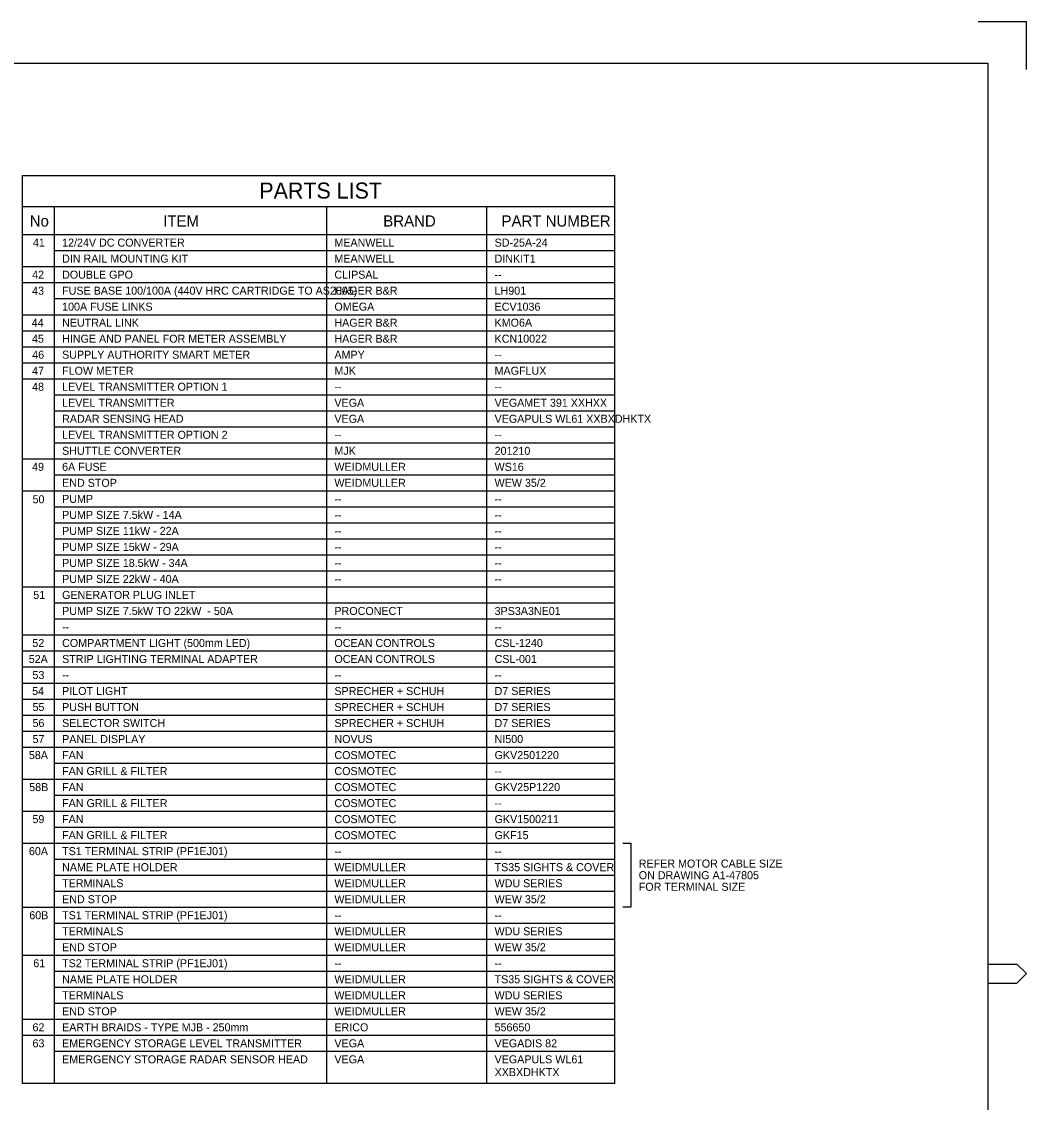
# Model space of a CAD drawing. Extents: x 0 to 841, y 0 to 594.
# Drawn here: x 527.4 to 841, y 256.6 to 594 of the extents above; entities that cross this region are included whole.
import ezdxf

# ---------------------------------------------------------------- set-up
doc = ezdxf.new("R2010")
doc.units = 0
for name, color, linetype in [('A1BORDER', 7, 'Continuous'), ('Default', 7, 'Continuous'), ('Level 1', 7, 'Continuous')]:
    doc.layers.add(name, color=color, linetype=linetype)

msp = doc.modelspace()

# ---------------------------------------------------------------- linework, layer by layer
at = {"layer": 'A1BORDER'}
for p, q in [((826, 594), (841, 594)), ((841, 579), (841, 594)), ((28, 581), (829, 581)), ((829, 581), (829, 15)), ((829, 299.76), (838, 299.76)), ((838, 299.76), (841, 296.76)), ((829, 293.76), (838, 293.76)), ((838, 293.76), (841, 296.76))]:
    msp.add_line(p, q, dxfattribs=at)
at = {"layer": 'Default'}
for p, q in [((537.5, 472.5), (712.5, 472.5)), ((537.5, 462.5), (712.5, 462.5)), ((527.5, 277.5), (712.5, 277.5)), ((537.5, 272.5), (712.5, 272.5))]:
    msp.add_line(p, q, dxfattribs=at)
msp.add_lwpolyline([(715, 337.5), (717.5, 337.5), (717.5, 317.5), (715, 317.5)], dxfattribs=at)
at = {"layer": 'Level 1'}
for p, q in [((527.5, 546), (527.5, 262.5)), ((527.5, 546), (712.5, 546)), ((712.5, 262.5), (712.5, 546)), ((527.5, 536.25), (712.5, 536.25)), ((537.5, 536.25), (537.5, 262.5)), ((622.5, 536.25), (622.5, 262.5)), ((672.5, 536.25), (672.5, 262.5)), ((527.5, 527.5), (712.5, 527.5)), ((537.5, 522.5), (712.5, 522.5)), ((527.5, 517.5), (712.5, 517.5)), ((527.5, 512.5), (712.5, 512.5)), ((537.5, 507.5), (712.5, 507.5)), ((527.5, 502.5), (712.5, 502.5)), ((527.5, 497.5), (712.5, 497.5)), ((527.5, 492.5), (712.5, 492.5)), ((527.5, 487.5), (712.5, 487.5)), ((527.5, 482.5), (712.5, 482.5)), ((537.5, 477.5), (712.5, 477.5)), ((537.5, 467.5), (712.5, 467.5)), ((527.5, 457.5), (712.5, 457.5)), ((537.5, 452.5), (712.5, 452.5)), ((527.5, 447.5), (712.5, 447.5)), ((537.5, 442.5), (712.5, 442.5)), ((537.5, 437.5), (712.5, 437.5)), ((537.5, 432.5), (712.5, 432.5)), ((537.5, 427.5), (712.5, 427.5)), ((537.5, 422.5), (712.5, 422.5)), ((527.5, 417.5), (712.5, 417.5)), ((537.5, 412.5), (712.5, 412.5)), ((537.5, 407.5), (712.5, 407.5)), ((527.5, 402.5), (712.5, 402.5)), ((527.5, 397.5), (712.5, 397.5)), ((527.5, 392.5), (712.5, 392.5)), ((527.5, 387.5), (712.5, 387.5)), ((527.5, 382.5), (712.5, 382.5)), ((527.5, 377.5), (712.5, 377.5)), ((527.5, 372.5), (712.5, 372.5)), ((527.5, 367.5), (712.5, 367.5)), ((537.5, 362.5), (712.5, 362.5)), ((527.5, 357.5), (712.5, 357.5)), ((537.5, 352.5), (712.5, 352.5)), ((527.5, 347.5), (712.5, 347.5)), ((537.5, 342.5), (712.5, 342.5)), ((527.5, 337.5), (712.5, 337.5)), ((537.5, 332.5), (712.5, 332.5)), ((537.5, 327.5), (712.5, 327.5)), ((537.5, 322.5), (712.5, 322.5)), ((527.5, 317.5), (712.5, 317.5)), ((537.5, 312.5), (712.5, 312.5)), ((537.5, 307.5), (712.5, 307.5)), ((527.5, 302.5), (712.5, 302.5)), ((537.5, 297.5), (712.5, 297.5)), ((537.5, 292.5), (712.5, 292.5)), ((537.5, 287.5), (712.5, 287.5)), ((527.5, 282.5), (712.5, 282.5)), ((712.5, 262.5), (527.5, 262.5))]:
    msp.add_line(p, q, dxfattribs=at)

# ---------------------------------------------------------------- texts
at = {"layer": 'Default'}
for s, p in [('LEVEL TRANSMITTER OPTION 1', (540, 478.75)), ('LEVEL TRANSMITTER', (540, 473.75)), ('VEGA', (625, 473.75)), ('VEGAMET 391 XXHXX', (675, 473.75)), ('RADAR SENSING HEAD', (540, 468.75)), ('VEGA', (625, 468.75)), ('VEGAPULS WL61 XXBXDHKTX', (675, 468.75)), ('LEVEL TRANSMITTER OPTION 2', (540, 463.75)), ('SHUTTLE CONVERTER', (540, 458.75)), ('MJK', (625, 458.75)), ('201210', (675, 458.75)), ('PUMP', (540, 443.75)), ('COMPARTMENT LIGHT (500mm LED)', (540, 398.75)), ('OCEAN CONTROLS', (625, 398.75)), ('CSL-1240', (675, 398.75)), ('STRIP LIGHTING TERMINAL ADAPTER', (540, 393.75)), ('OCEAN CONTROLS', (625, 393.75)), ('CSL-001', (675, 393.75)), ('62', (530.76, 278.75)), ('63', (530.76, 273.75)), ('EMERGENCY STORAGE LEVEL TRANSMITTER', (540, 273.75)), ('VEGA', (625, 273.75)), ('VEGADIS 82', (675, 273.75)), ('EMERGENCY STORAGE RADAR SENSOR HEAD', (540, 268.75)), ('VEGA', (625, 268.75)), ('VEGAPULS WL61', (675, 268.75)), ('XXBXDHKTX', (675, 264.75))]:
    msp.add_text(s, height=2.5, dxfattribs=at).set_placement(p)
at = {"layer": 'Level 1'}
for s, height, p in [('PARTS LIST', 5, (601.57, 538.75)), ('No', 3.5, (529.89, 530)), ('ITEM', 3.5, (571.54, 530)), ('BRAND', 3.5, (640.25, 530)), ('PART NUMBER', 3.5, (677.16, 530)), ('41', 2.5, (530.88, 523.75)), ('12/24V DC CONVERTER', 2.5, (540, 523.75)), ('MEANWELL', 2.5, (625, 523.75)), ('SD-25A-24', 2.5, (675, 523.75)), ('DIN RAIL MOUNTING KIT', 2.5, (540, 518.75)), ('MEANWELL', 2.5, (625, 518.75)), ('DINKIT1', 2.5, (675, 518.75)), ('42', 2.5, (530.66, 513.75)), ('DOUBLE GPO', 2.5, (540, 513.75)), ('CLIPSAL', 2.5, (625, 513.75)), ('--', 2.5, (675, 513.75)), ('43', 2.5, (530.63, 508.75)), ('FUSE BASE 100/100A (440V HRC CARTRIDGE TO AS2005)', 2.5, (540, 508.75)), ('HAGER B&R', 2.5, (625, 508.75)), ('LH901', 2.5, (675, 508.75)), ('100A FUSE LINKS', 2.5, (540, 503.75)), ('OMEGA', 2.5, (625, 503.75)), ('ECV1036', 2.5, (675, 503.75)), ('44', 2.5, (530.51, 498.75)), ('NEUTRAL LINK', 2.5, (540, 498.75)), ('HAGER B&R', 2.5, (625, 498.75)), ('KMO6A', 2.5, (675, 498.75)), ('45', 2.5, (530.59, 493.75)), ('HINGE AND PANEL FOR METER ASSEMBLY', 2.5, (540, 493.75)), ('HAGER B&R', 2.5, (625, 493.75)), ('KCN10022', 2.5, (675, 493.75)), ('46', 2.5, (530.66, 488.75)), ('SUPPLY AUTHORITY SMART METER', 2.5, (540, 488.75)), ('AMPY', 2.5, (625, 488.75)), ('--', 2.5, (675, 488.75)), ('47', 2.5, (530.63, 483.75)), ('FLOW METER', 2.5, (540, 483.75)), ('MJK', 2.5, (625, 483.75)), ('MAGFLUX', 2.5, (675, 483.75)), ('48', 2.5, (530.63, 478.75)), ('--', 2.5, (625, 478.75)), ('--', 2.5, (675, 478.75)), ('--', 2.5, (625, 463.75)), ('--', 2.5, (675, 463.75)), ('49', 2.5, (530.63, 453.75)), ('6A FUSE', 2.5, (540, 453.75)), ('WEIDMULLER', 2.5, (625, 453.75)), ('WS16', 2.5, (675, 453.75)), ('END STOP', 2.5, (540, 448.75)), ('WEIDMULLER', 2.5, (625, 448.75)), ('WEW 35/2', 2.5, (675, 448.75)), ('50', 2.5, (530.76, 443.62)), ('--', 2.5, (625, 443.75)), ('--', 2.5, (675, 443.75)), ('PUMP SIZE 7.5kW - 14A', 2.5, (540, 438.75)), ('--', 2.5, (625, 438.75)), ('--', 2.5, (675, 438.75)), ('PUMP SIZE 11kW - 22A', 2.5, (540, 433.75)), ('--', 2.5, (625, 433.75)), ('--', 2.5, (675, 433.75)), ('PUMP SIZE 15kW - 29A', 2.5, (540, 428.75)), ('--', 2.5, (625, 428.75)), ('--', 2.5, (675, 428.75)), ('PUMP SIZE 18.5kW - 34A', 2.5, (540, 423.75)), ('--', 2.5, (625, 423.75)), ('--', 2.5, (675, 423.75)), ('PUMP SIZE 22kW - 40A', 2.5, (540, 418.75)), ('--', 2.5, (625, 418.75)), ('--', 2.5, (675, 418.75)), ('51', 2.5, (531.01, 413.75)), ('GENERATOR PLUG INLET', 2.5, (540, 413.75)), ('PUMP SIZE 7.5kW TO 22kW  - 50A', 2.5, (540, 408.75)), ('PROCONECT', 2.5, (625, 408.75)), ('3PS3A3NE01', 2.5, (675, 408.75)), ('--', 2.5, (540, 403.75)), ('--', 2.5, (625, 403.75)), ('--', 2.5, (675, 403.75)), ('52', 2.5, (530.71, 398.75)), ('52A', 2.5, (529.59, 393.75)), ('53', 2.5, (530.74, 388.75)), ('--', 2.5, (540, 388.75)), ('--', 2.5, (625, 388.75)), ('--', 2.5, (675, 388.75)), ('54', 2.5, (530.63, 383.75)), ('PILOT LIGHT', 2.5, (540, 383.75)), ('SPRECHER + SCHUH', 2.5, (625, 383.75)), ('D7 SERIES', 2.5, (675, 383.75)), ('55', 2.5, (530.76, 378.75)), ('PUSH BUTTON', 2.5, (540, 378.75)), ('SPRECHER + SCHUH', 2.5, (625, 378.75)), ('D7 SERIES', 2.5, (675, 378.75)), ('56', 2.5, (530.76, 373.75)), ('SELECTOR SWITCH', 2.5, (540, 373.75)), ('SPRECHER + SCHUH', 2.5, (625, 373.75)), ('D7 SERIES', 2.5, (675, 373.75)), ('57', 2.5, (530.76, 368.75)), ('PANEL DISPLAY', 2.5, (540, 368.75)), ('NOVUS', 2.5, (625, 368.75)), ('NI500', 2.5, (675, 368.75)), ('58A', 2.5, (529.62, 363.75)), ('FAN', 2.5, (540, 363.75)), ('COSMOTEC', 2.5, (625, 363.75)), ('GKV2501220', 2.5, (675, 363.75)), ('FAN GRILL & FILTER', 2.5, (540, 358.75)), ('COSMOTEC', 2.5, (625, 358.75)), ('--', 2.5, (675, 358.75)), ('58B', 2.5, (529.74, 353.75)), ('FAN', 2.5, (540, 353.75)), ('COSMOTEC', 2.5, (625, 353.75)), ('GKV25P1220', 2.5, (675, 353.75)), ('FAN GRILL & FILTER', 2.5, (540, 348.75)), ('COSMOTEC', 2.5, (625, 348.75)), ('--', 2.5, (675, 348.75)), ('59', 2.5, (530.74, 343.75)), ('FAN', 2.5, (540, 343.75)), ('COSMOTEC', 2.5, (625, 343.75)), ('GKV1500211', 2.5, (675, 343.75)), ('FAN GRILL & FILTER', 2.5, (540, 338.75)), ('COSMOTEC', 2.5, (625, 338.75)), ('GKF15', 2.5, (675, 338.75)), ('60A', 2.5, (529.64, 333.75)), ('TS1 TERMINAL STRIP (PF1EJ01)', 2.5, (540, 333.75)), ('--', 2.5, (625, 333.75)), ('--', 2.5, (675, 333.75)), ('NAME PLATE HOLDER', 2.5, (540, 328.75)), ('WEIDMULLER', 2.5, (625, 328.75)), ('TS35 SIGHTS & COVER', 2.5, (675, 328.75)), ('REFER MOTOR CABLE SIZE', 2.5, (720, 329.87)), ('ON DRAWING A1-47805', 2.5, (720, 326.25)), ('TERMINALS', 2.5, (540, 323.75)), ('WEIDMULLER', 2.5, (625, 323.75)), ('WDU SERIES', 2.5, (675, 323.75)), ('FOR TERMINAL SIZE', 2.5, (720, 322.63)), ('END STOP', 2.5, (540, 318.75)), ('WEIDMULLER', 2.5, (625, 318.75)), ('WEW 35/2', 2.5, (675, 318.75)), ('60B', 2.5, (529.76, 313.75)), ('TS1 TERMINAL STRIP (PF1EJ01)', 2.5, (540, 313.75)), ('--', 2.5, (625, 313.75)), ('--', 2.5, (675, 313.75)), ('TERMINALS', 2.5, (540, 308.75)), ('WEIDMULLER', 2.5, (625, 308.75)), ('WDU SERIES', 2.5, (675, 308.75)), ('END STOP', 2.5, (540, 303.75)), ('WEIDMULLER', 2.5, (625, 303.75)), ('WEW 35/2', 2.5, (675, 303.75)), ('61', 2.5, (531.01, 298.75)), ('TS2 TERMINAL STRIP (PF1EJ01)', 2.5, (540, 298.75)), ('--', 2.5, (625, 298.75)), ('--', 2.5, (675, 298.75)), ('NAME PLATE HOLDER', 2.5, (540, 293.75)), ('WEIDMULLER', 2.5, (625, 293.75)), ('TS35 SIGHTS & COVER', 2.5, (675, 293.75)), ('TERMINALS', 2.5, (540, 288.75)), ('WEIDMULLER', 2.5, (625, 288.75)), ('WDU SERIES', 2.5, (675, 288.75)), ('END STOP', 2.5, (540, 283.75)), ('WEIDMULLER', 2.5, (625, 283.75)), ('WEW 35/2', 2.5, (675, 283.75)), ('EARTH BRAIDS - TYPE MJB - 250mm', 2.5, (540, 278.75)), ('ERICO', 2.5, (625, 278.75)), ('556650', 2.5, (675, 278.75))]:
    msp.add_text(s, height=height, dxfattribs=at).set_placement(p)

doc.saveas('drawing.dxf')
